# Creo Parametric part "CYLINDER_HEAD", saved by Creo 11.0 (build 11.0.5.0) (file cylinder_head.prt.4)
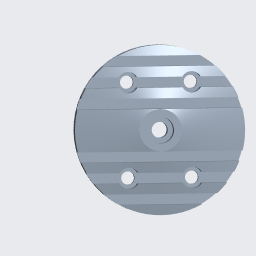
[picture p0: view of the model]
Materials in the file: 10038_S235JR

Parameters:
  MATERIAL = "10038_S235JR"
  PTC_MATERIAL_NAME = "10038_S235JR"
  PTC_MASTER_MATERIAL = "10038_S235JR"
  SELECT_EN_NAME = "S235JR"
  SELECT_DIN_NAME = "RSt37-2"
  SELECT_MATERIAL_NUMBER = "1.0038"
  SELECT_ASTM_NAME = "A 283 M Grade 2"
  MATERIAL_GROUP = "ME_ST_Baustahl"
  STANDARD_EN_DELIVERYSPEC = "DIN EN 10025-2"
  STANDARD_DIN_DELIVERYSPEC = "DIN EN 10025-2"

Other parameters: GEWICHT

Created from: STARTTEIL.PRT

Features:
  1. datum plane "RIGHT"
  2. datum plane "TOP"
  3. datum plane "FRONT"
  4. coordinate system
  5. datum axis
  6. datum axis
  7. datum axis
  8. revolve "Revolve 1"
  9. pattern "Pattern 1"
  10. extruded cut "Extrude 1"
  11. extruded cut "Extrude 1 [2]"
  12. extruded cut "Extrude 1 [3]"
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
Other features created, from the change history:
  extrusion "Extrude 1"
  mirror "Mirror 1"
  pattern "Pattern 1 (2)"
  extruded cut "Extrude 1 (2) [1]"
  extruded cut "Extrude 1 (2) [2]"
  extruded cut "Extrude 1 (2) [3]"
  mirror "Mirror 2"
  pattern "Pattern 1 (3)"
  extruded cut "Extrude 1 (3) [1]"
  extruded cut "Extrude 1 (3) [2]"
  extruded cut "Extrude 1 (3) [3]"
  mirror "Mirror 3"
  pattern "Pattern 1 (4)"
  extruded cut "Extrude 1 (4) [1]"
  extruded cut "Extrude 1 (4) [2]"
  extruded cut "Extrude 1 (4) [3]"
  extruded cut "Extrude 2"
  extruded cut "Extrude 3"
  mirror "Mirror 4"
  extruded cut "Extrude 3 (2)"
  mirror "Mirror 5"
  extruded cut "Extrude 3 (3)"
  mirror "Mirror 6"
  extruded cut "Extrude 3 (4)"
  extruded cut "Extrude 4"
  extruded cut "Extrude 5"
  mirror "Mirror 7"
  extruded cut "Extrude 5 (2)"
  mirror "Mirror 8"
  extruded cut "Extrude 5 (3)"
  mirror "Mirror 9"
  extruded cut "Extrude 5 (4)"

Other named items: A_Y, A_X, A_Z, CS0

Layers: BEZUGSACHSEN

Surfaces: 21 plane, 12 cylinder, 2 cone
